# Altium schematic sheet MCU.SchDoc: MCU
size 431 x 279 mm; DocumentNumber: 10000020916; Revision: 000; SheetNumber: 4; SheetTotal: 10; DESCRIPTION REVISION 1 LOG: RELEASE FOR PROTOTYPE; ProjectTitle: Industrial IOT Sensor
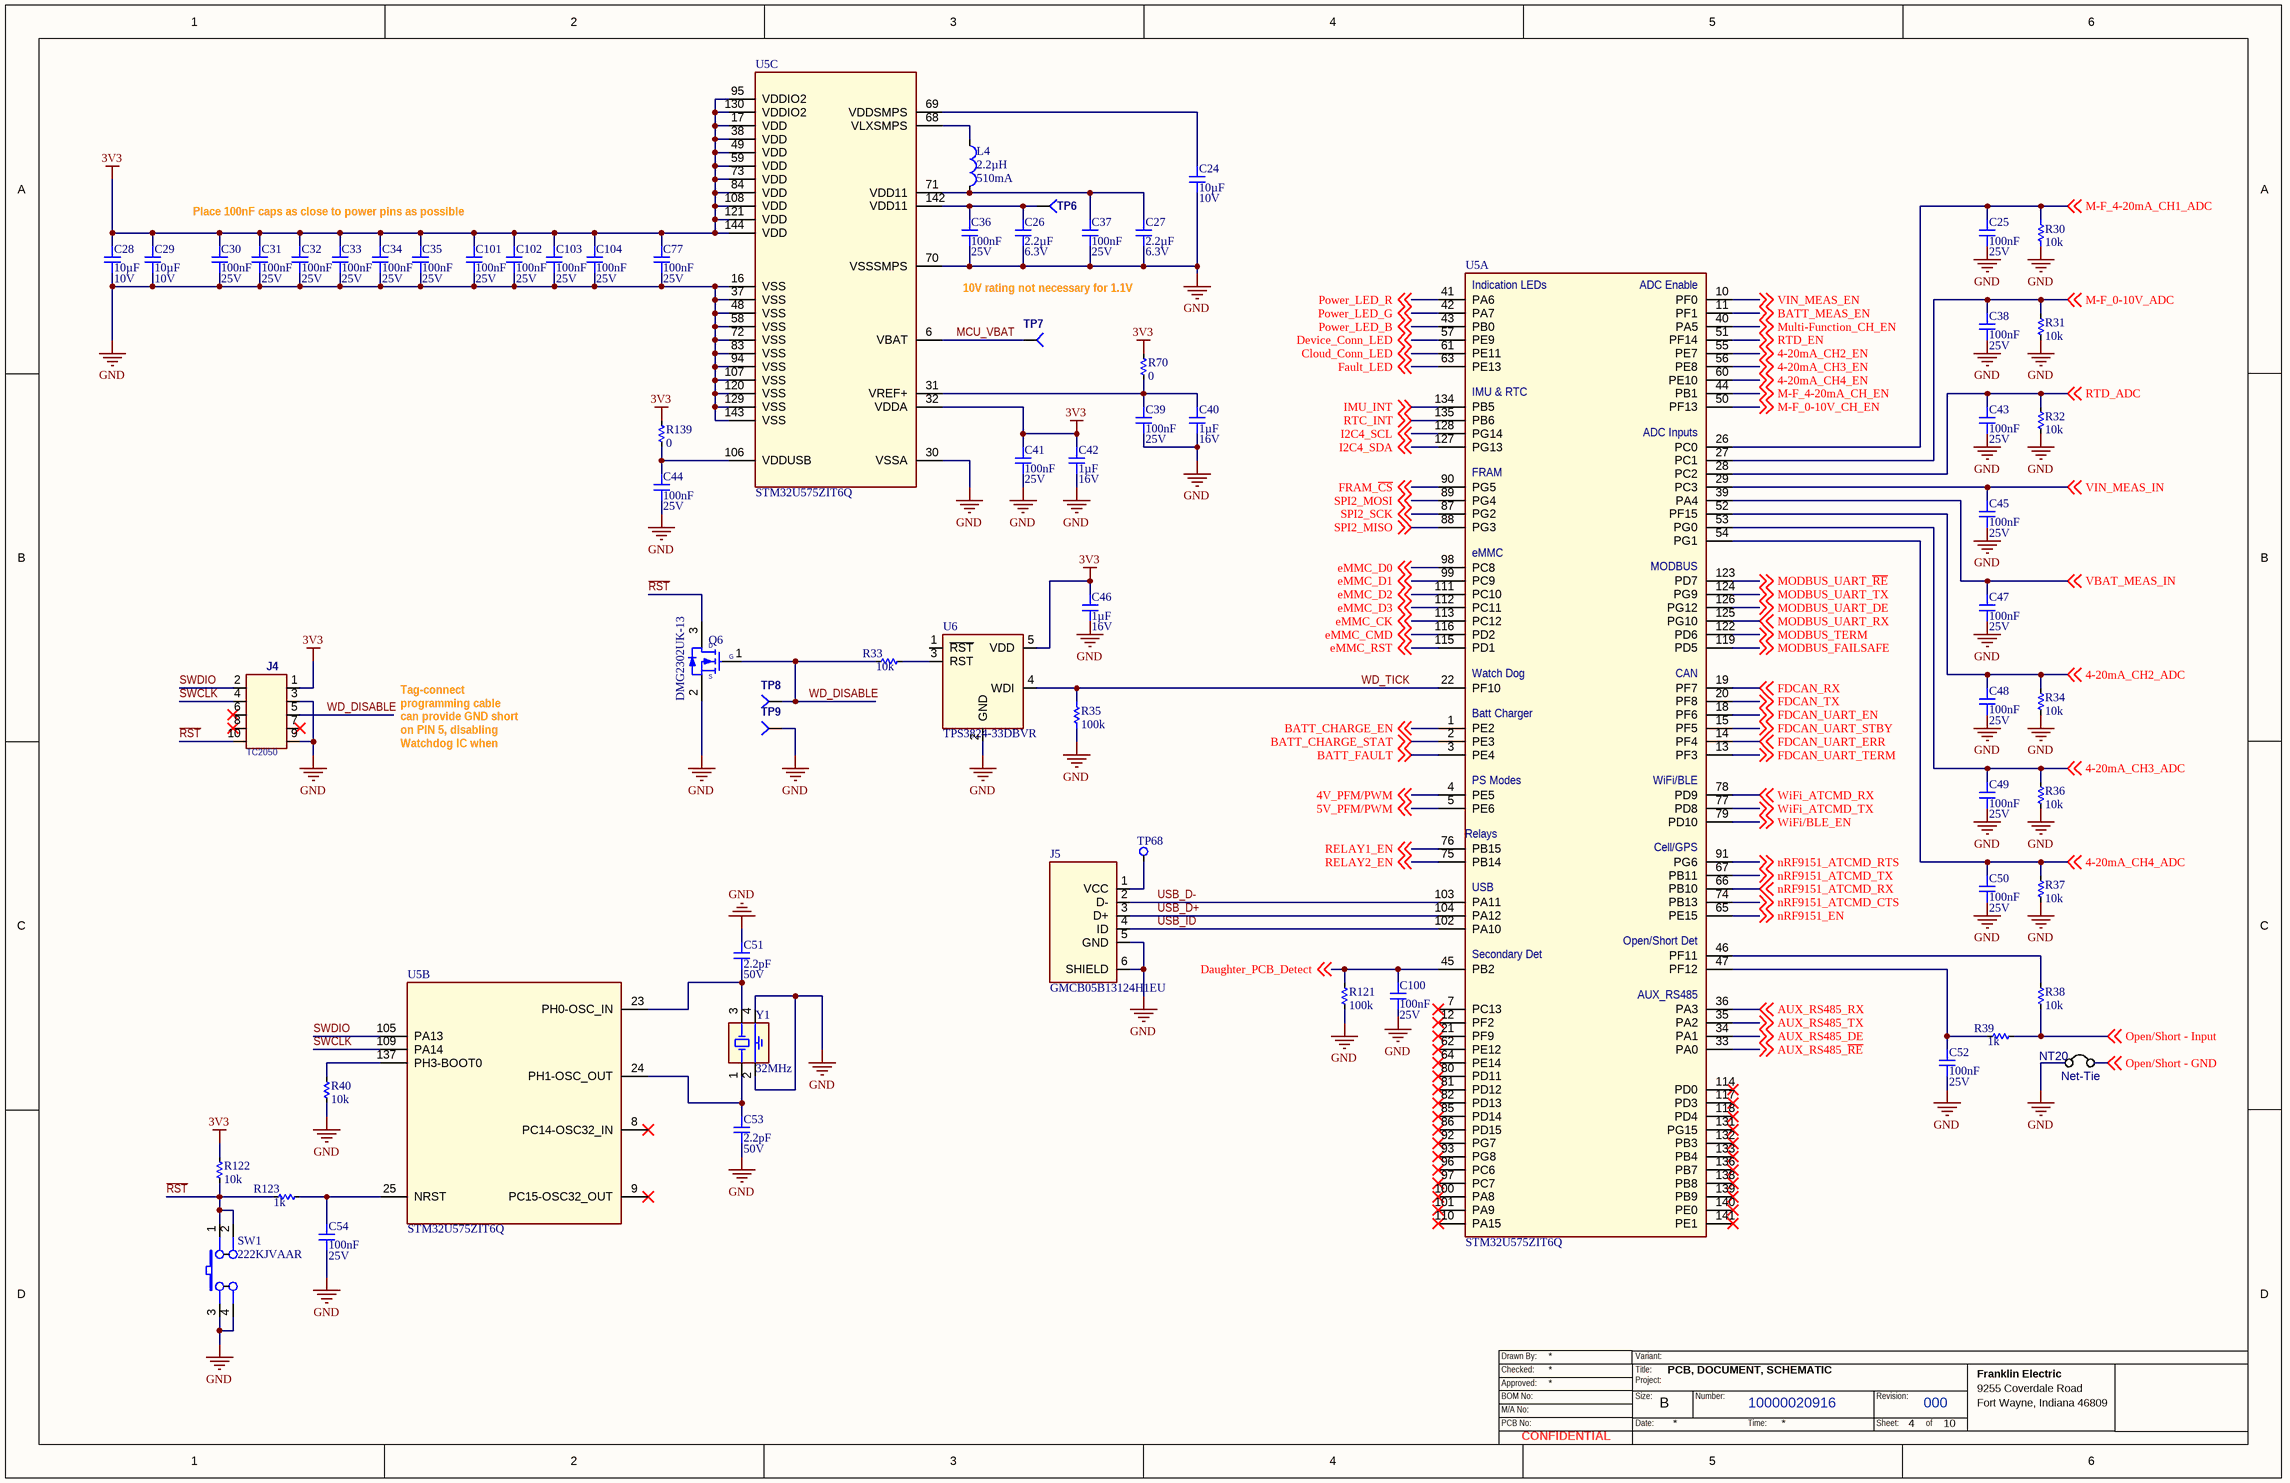
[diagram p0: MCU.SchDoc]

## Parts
C24  10µF  Voltage Rating DC: 10V  [CAPC1608X90N]
C25  100nF  Voltage Rating DC: 25V  [CAPC1005X60N]
C26  2.2µF  Voltage Rating DC: 6.3V  [CAPC1005X60N]
C27  2.2µF  Voltage Rating DC: 6.3V  [CAPC1005X60N]
C28  10µF  Voltage Rating DC: 10V  [CAPC1608X90N]
C29  10µF  Voltage Rating DC: 10V  [CAPC1608X90N]
C30  100nF  Voltage Rating DC: 25V  [CAPC1005X60N]
C31  100nF  Voltage Rating DC: 25V  [CAPC1005X60N]
C32  100nF  Voltage Rating DC: 25V  [CAPC1005X60N]
C33  100nF  Voltage Rating DC: 25V  [CAPC1005X60N]
C34  100nF  Voltage Rating DC: 25V  [CAPC1005X60N]
C35  100nF  Voltage Rating DC: 25V  [CAPC1005X60N]
C36  100nF  Voltage Rating DC: 25V  [CAPC1005X60N]
C37  100nF  Voltage Rating DC: 25V  [CAPC1005X60N]
C38  100nF  Voltage Rating DC: 25V  [CAPC1005X60N]
C39  100nF  Voltage Rating DC: 25V  [CAPC1005X60N]
C40  1µF  Voltage Rating DC: 16V  [CAPC1005X60N]
C41  100nF  Voltage Rating DC: 25V  [CAPC1005X60N]
C42  1µF  Voltage Rating DC: 16V  [CAPC1005X60N]
C43  100nF  Voltage Rating DC: 25V  [CAPC1005X60N]
C44  100nF  Voltage Rating DC: 25V  [CAPC1005X60N]
C45  100nF  Voltage Rating DC: 25V  [CAPC1005X60N]
C46  1µF  Voltage Rating DC: 16V  [CAPC1005X60N]
C47  100nF  Voltage Rating DC: 25V  [CAPC1005X60N]
C48  100nF  Voltage Rating DC: 25V  [CAPC1005X60N]
C49  100nF  Voltage Rating DC: 25V  [CAPC1005X60N]
C50  100nF  Voltage Rating DC: 25V  [CAPC1005X60N]
C51  2.2pF  Voltage Rating DC: 50V  [CAPC1005X60N]
C52  100nF  Voltage Rating DC: 25V  [CAPC1005X60N]
C53  2.2pF  Voltage Rating DC: 50V  [CAPC1005X60N]
C54  100nF  Voltage Rating DC: 25V  [CAPC1005X60N]
C77  100nF  Voltage Rating DC: 25V  [CAPC1005X60N]
C100  100nF  Voltage Rating DC: 25V  [CAPC1005X60N]
C101  100nF  Voltage Rating DC: 25V  [CAPC1005X60N]
C102  100nF  Voltage Rating DC: 25V  [CAPC1005X60N]
C103  100nF  Voltage Rating DC: 25V  [CAPC1005X60N]
C104  100nF  Voltage Rating DC: 25V  [CAPC1005X60N]
J4  value TC2050  [TC2050_NL]  (hidden comment: J_CONN TC2050)  (no BOM)
J5  GMCB05B13124H1EU  [USB 2.0 MICRO B]
L4  2.2µH  Rated Current: 510mA  [INDA251818-A]
NT20  Net-Tie  [NT-40mil-No Mask/No Silk]  (net tie, no BOM)
Q6  DMG2302UK-13  [SOT90P225X100-3N]
R30  10k  [RESC1005N]
R31  10k  [RESC1005N]
R32  10k  [RESC1005N]
R33  10k  [RESC1005N]
R34  10k  [RESC1005N]
R35  100k  [RESC1005N]
R36  10k  [RESC1005N]
R37  10k  [RESC1005N]
R38  10k  [RESC1005N]
R39  1k  [RESC1005N]
R40  10k  [RESC1005N]
R70  0  [RESC1005N]
R121  100k  [RESC1005N]
R122  10k  [RESC1005N]
R123  1k  [RESC1005N]
R139  0  [RESC1005N]
SW1  222KJVAAR  [6.2x6.2x5.2 Tactile SW J-Lead]
TP6  TEST POINT, SMD PAD, .050 DIA  [TESTPOINT_SMD_ROUND_50]  (value not drawn)
TP7  TEST POINT, SMD PAD, .050 DIA  [TESTPOINT_SMD_ROUND_50]  (value not drawn)
TP8  TEST POINT, SMD PAD, .050 DIA  [TESTPOINT_SMD_ROUND_50]  (value not drawn)
TP9  TEST POINT, SMD PAD, .050 DIA  [TESTPOINT_SMD_ROUND_50]  (value not drawn)
TP68  Test Points  [TP030SMD]  (value not drawn)  (no BOM)
U5  STM32U575ZIT6Q  [144-LQFP (20x20)]  (parts A,B,C of 3)
U6  TPS3824-33DBVR  [SOT23-5]
Y1  32MHz  [OSC4P200X160X59_ABM1132M-A]

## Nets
3V3: C28.1 C29.1 C30.1 C31.1 C32.1 C33.1 C34.1 C35.1 C41.1 C42.1 C46.1 C77.1 C101.1 C102.1 C103.1 C104.1 J4.1 R70.1 R122.1 R139.1 U5.17(VDD) U5.32(VDDA) U5.38(VDD) U5.49(VDD) U5.59(VDD) U5.73(VDD) U5.84(VDD) U5.95(VDDIO2) U5.108(VDD) U5.121(VDD) U5.130(VDDIO2) U5.144(VDD) U6.5(VDD)
GND: C24.2 C25.2 C26.2 C27.2 C28.2 C29.2 C30.2 C31.2 C32.2 C33.2 C34.2 C35.2 C36.2 C37.2 C38.2 C39.2 C40.2 C41.2 C42.2 C43.2 C44.2 C45.2 C46.2 C47.2 C48.2 C49.2 C50.2 C51.1 C52.2 C53.2 C54.2 C77.2 C100.2 C101.2 C102.2 C103.2 C104.2 J4.3 J4.9 J5.5(GND) J5.6(SHIELD) NT20.1 Q6.2(Source) R30.2 R31.2 R32.2 R34.2 R35.2 R36.2 R37.2 R40.2 R121.2 SW1.3 SW1.4 TP9.1(TP) U5.16(VSS) U5.30(VSSA) U5.37(VSS) U5.48(VSS) U5.58(VSS) U5.70(VSSSMPS) U5.72(VSS) U5.83(VSS) U5.94(VSS) U5.107(VSS) U5.120(VSS) U5.129(VSS) U5.143(VSS) U6.2(GND) Y1.2(GND) Y1.4(GND)
4-20mA_CH2_ADC: C48.1 R34.1 U5.52(PF15) ; off-sheet 4-20mA_CH2_ADC
4-20mA_CH2_EN: U5.55(PE7) ; off-sheet 4-20mA_CH2_EN
4-20mA_CH3_ADC: C49.1 R36.1 U5.53(PG0) ; off-sheet 4-20mA_CH3_ADC
4-20mA_CH3_EN: U5.56(PE8) ; off-sheet 4-20mA_CH3_EN
4-20mA_CH4_ADC: C50.1 R37.1 U5.54(PG1) ; off-sheet 4-20mA_CH4_ADC
4-20mA_CH4_EN: U5.60(PE10) ; off-sheet 4-20mA_CH4_EN
4V_PFM/PWM: U5.4(PE5) ; off-sheet 4V_PFM/PWM
5V_PFM/PWM: U5.5(PE6) ; off-sheet 5V_PFM/PWM
AUX_RS485_DE: U5.34(PA1) ; off-sheet AUX_RS485_DE
AUX_RS485_~{RE}: U5.33(PA0) ; off-sheet AUX_RS485_~{RE}
AUX_RS485_RX: U5.36(PA3) ; off-sheet AUX_RS485_RX
AUX_RS485_TX: U5.35(PA2) ; off-sheet AUX_RS485_TX
BATT_CHARGE_EN: U5.1(PE2) ; off-sheet BATT_CHARGE_EN
BATT_CHARGE_STAT: U5.2(PE3) ; off-sheet BATT_CHARGE_STAT
BATT_FAULT: U5.3(PE4) ; off-sheet BATT_FAULT
BATT_MEAS_EN: U5.11(PF1) ; off-sheet BATT_MEAS_EN
Cloud_Conn_LED: U5.61(PE11) ; off-sheet Cloud_Conn_LED
Daughter_PCB_Detect: C100.1 R121.1 U5.45(PB2) ; off-sheet Daughter_PCB_Detect
Device_Conn_LED: U5.57(PE9) ; off-sheet Device_Conn_LED
eMMC_CK: U5.113(PC12) ; off-sheet eMMC_CK
eMMC_CMD: U5.116(PD2) ; off-sheet eMMC_CMD
eMMC_D0: U5.98(PC8) ; off-sheet eMMC_D0
eMMC_D1: U5.99(PC9) ; off-sheet eMMC_D1
eMMC_D2: U5.111(PC10) ; off-sheet eMMC_D2
eMMC_D3: U5.112(PC11) ; off-sheet eMMC_D3
eMMC_RST: U5.115(PD1) ; off-sheet eMMC_RST
Fault_LED: U5.63(PE13) ; off-sheet Fault_LED
FDCAN_RX: U5.19(PF7) ; off-sheet FDCAN_RX
FDCAN_TX: U5.20(PF8) ; off-sheet FDCAN_TX
FDCAN_UART_EN: U5.18(PF6) ; off-sheet FDCAN_UART_EN
FDCAN_UART_ERR: U5.14(PF4) ; off-sheet FDCAN_UART_ERR
FDCAN_UART_STBY: U5.15(PF5) ; off-sheet FDCAN_UART_STBY
FDCAN_UART_TERM: U5.13(PF3) ; off-sheet FDCAN_UART_TERM
FRAM_~{CS}: U5.90(PG5) ; off-sheet FRAM_~{CS}
I2C4_SCL: U5.128(PG14) ; off-sheet I2C4_SCL
I2C4_SDA: U5.127(PG13) ; off-sheet I2C4_SDA
IMU_INT: U5.134(PB5) ; off-sheet IMU_INT
M-F_0-10V_ADC: C38.1 R31.1 U5.27(PC1) ; off-sheet M-F_0-10V_ADC
M-F_0-10V_CH_EN: U5.50(PF13) ; off-sheet M-F_0-10V_CH_EN
M-F_4-20mA_CH1_ADC: C25.1 R30.1 U5.26(PC0) ; off-sheet M-F_4-20mA_CH1_ADC
M-F_4-20mA_CH_EN: U5.44(PB1) ; off-sheet M-F_4-20mA_CH_EN
MCU_VBAT: TP7.1(TP) U5.6(VBAT)
MODBUS_FAILSAFE: U5.119(PD5) ; off-sheet MODBUS_FAILSAFE
MODBUS_TERM: U5.122(PD6) ; off-sheet MODBUS_TERM
MODBUS_UART_DE: U5.126(PG12) ; off-sheet MODBUS_UART_DE
MODBUS_UART_~{RE}: U5.123(PD7) ; off-sheet MODBUS_UART_~{RE}
MODBUS_UART_RX: U5.125(PG10) ; off-sheet MODBUS_UART_RX
MODBUS_UART_TX: U5.124(PG9) ; off-sheet MODBUS_UART_TX
Multi-Function_CH_EN: U5.40(PA5) ; off-sheet Multi-Function_CH_EN
nRF9151_ATCMD_CTS: U5.74(PB13) ; off-sheet nRF9151_ATCMD_CTS
nRF9151_ATCMD_RTS: U5.91(PG6) ; off-sheet nRF9151_ATCMD_RTS
nRF9151_ATCMD_RX: U5.66(PB10) ; off-sheet nRF9151_ATCMD_RX
nRF9151_ATCMD_TX: U5.67(PB11) ; off-sheet nRF9151_ATCMD_TX
nRF9151_EN: U5.65(PE15) ; off-sheet nRF9151_EN
Open/Short - GND: NT20.2 ; off-sheet Open/Short - GND
Open/Short - Input: R38.2 R39.2 ; off-sheet Open/Short - Input
Power_LED_B: U5.43(PB0) ; off-sheet Power_LED_B
Power_LED_G: U5.42(PA7) ; off-sheet Power_LED_G
Power_LED_R: U5.41(PA6) ; off-sheet Power_LED_R
~{RST}: J4.10 Q6.3(Drain) R122.2 R123.1 SW1.1 SW1.2
RELAY1_EN: U5.76(PB15) ; off-sheet RELAY1_EN
RELAY2_EN: U5.75(PB14) ; off-sheet RELAY2_EN
RTC_INT: U5.135(PB6) ; off-sheet RTC_INT
RTD_ADC: C43.1 R32.1 U5.28(PC2) ; off-sheet RTD_ADC
RTD_EN: U5.51(PF14) ; off-sheet RTD_EN
SPI2_MISO: U5.88(PG3) ; off-sheet SPI2_MISO
SPI2_MOSI: U5.89(PG4) ; off-sheet SPI2_MOSI
SPI2_SCK: U5.87(PG2) ; off-sheet SPI2_SCK
SWCLK: J4.4 U5.109(PA14)
SWDIO: J4.2 U5.105(PA13)
USB_D+: J5.3(D+) U5.104(PA12)
USB_D-: J5.2(D-) U5.103(PA11)
USB_ID: J5.4(ID) U5.102(PA10)
VBAT_MEAS_IN: C47.1 U5.39(PA4) ; off-sheet VBAT_MEAS_IN
VIN_MEAS_EN: U5.10(PF0) ; off-sheet VIN_MEAS_EN
VIN_MEAS_IN: C45.1 U5.29(PC3) ; off-sheet VIN_MEAS_IN
WD_DISABLE: J4.5 Q6.1(Gate) R33.1 TP8.1(TP)
WD_TICK: R35.1 U5.22(PF10) U6.4(WDI)
WiFi/BLE_EN: U5.79(PD10) ; off-sheet WiFi/BLE_EN
WiFi_ATCMD_RX: U5.78(PD9) ; off-sheet WiFi_ATCMD_RX
WiFi_ATCMD_TX: U5.77(PD8) ; off-sheet WiFi_ATCMD_TX
NetC24_1: C24.1 U5.69(VDDSMPS)
NetC26_1: C26.1 C36.1 TP6.1(TP) U5.142(VDD11)
NetC27_1: C27.1 C37.1 L4.2 U5.71(VDD11)
NetC39_1: C39.1 C40.1 R70.2 U5.31(VREF+)
NetC44_1: C44.1 R139.2 U5.106(VDDUSB)
NetC51_2: C51.2 U5.23(PH0-OSC_IN) Y1.3(X)
NetC52_1: C52.1 R39.1 U5.47(PF12)
NetC53_1: C53.1 U5.24(PH1-OSC_OUT) Y1.1(X)
NetC54_1: C54.1 R123.2 U5.25(NRST)
NetJ5_1: J5.1(VCC) TP68.1
NetL4_1: L4.1 U5.68(VLXSMPS)
NetR33_2: R33.2 U6.3(RST)
NetR38_1: R38.1 U5.46(PF11)
NetR40_1: R40.1 U5.137(PH3-BOOT0)

Not connected (* = marked no-connect by the designer): J4 6* 7* 8*; U5 7(PC13)* 8(PC14-OSC32_IN)* 9(PC15-OSC32_OUT)* 12(PF2)* 21(PF9)* 62(PE12)* 64(PE14)* 80(PD11)* 81(PD12)* 82(PD13)* 85(PD14)* 86(PD15)* 92(PG7)* 93(PG8)* 96(PC6)* 97(PC7)* 100(PA8)* 101(PA9)* 110(PA15)* 114(PD0)* 117(PD3)* 118(PD4)* 131(PG15)* 132(PB3)* 133(PB4)* 136(PB7)* 138(PB8)* 139(PB9)* 140(PE0)* 141(PE1)*; U6 1(~{RST})

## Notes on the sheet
- Place 100nF caps as close to power pins as possible
- 10V rating not necessary for 1.1V rail
- Tag-connect programming cable can provide GND short on PIN 5, disabling Watchdog IC when connected

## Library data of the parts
C24 C28 C29 = CMP-003-0109-42: CAP CER SMD 0603 10V 10% 10uF X5R; MFR1: Murata; MFR2PN: CL10A106KP8NNND; MFR3PN: 0603X106K100CT; MFR1PN: GRM188R61A106KE69D; FEPN: 227000148; Op Temp Max: 85°C; Agency Restriction: No; Op Temp Min: -55°C
C25 C30-C39 C41 C43-C45 C47-C50 C52 C54 C77 C100-C104 = CMP-00599-2: CAP CER SMD 0402 (1005) 25V 10% 0.1UF X7R; MFR2PN: 04023C104KAT2A; MFR1PN: CGA2B3X7R1E104K; MFR3PN: CL05B104KA5NNNC; MFR1: TDK; MFR4PN: TMK105B7104KVHF; FEPN: 228685108; Agency Restriction: N; Op Temp Min: -55°C; Op Temp Max: 125°C; Voltage Rating AC: 0V
C26 C27 = CMP-01677-1: CAP CER SMD 0402 6.3V 10% 2.2uF X5R; MFR1PN: CC0402KRX5R6BB225; MFR1: YAGEO; Agency Restriction: None; Op Temp Min: -55°C; Op Temp Max: 85°C; Voltage Rating AC: 0V; FEPN: 10000022637
C40 C42 C46 = CMP-019-0104-35: CAP CER SMD 0402 16V 10% 1UF X7R; MFR3PN: EMK105BJ105KV-F; MFR1PN: CL05A105KL5NRNC; MFR4PN: C1005X5R1C105K050BC; MFR2PN: EMK105BJ105KVHF; MFR1: Samsung; FEPN: 228685109; Agency Restriction: No; Op Temp Min: -55°C; Op Temp Max: 85°C
C51 C53 = CMP-01678-1: CAP CER SMD  0402 50V +/-.25pF 2.2pF C0G; MFR1PN: GJM1555C1H2R2CB01D; MFR1: MURATA; Agency Restriction: None; Op Temp Max: 125°C; FEPN: 10000022638; Op Temp Min: -55°C; Tolerance: 0%
J4 = J_CONN TC2050: DNA - TC2030-MCP Plug-of-Nails Programming Terminals (PCB Feature)(Do Not Assemble); Part_Type: Miscellaneous; FPLIST: TC2030,TC2030_SP
J5 = CMP-01736-2: CONNECTOR, INTERFACE, USBUB USB2.0 POST VERTICAL; MFR1: AMPHENOL; Current Rating: 1.8A; Agency Restriction: None; Op Temp Max: 85°C; FEPN: 10000023422; Op Temp Min: -40°C; Number Of Positions: 5; Voltage Rating: 30V
L4 = CMP-01703-2: INDUCTOR, FIXED, SURFACE MOUNT 2.2uH 510mA 117mOHM; MFR1: TAIYO YUDEN; MFR1PN: LSQNA251818T2R2M; FEPN: 10000023000; Saturation Current: 950mA; Tolerance: 20%; Type: Unshielded Wirewound; Op Temp Max: 105°C; Agency Restriction: N; Op Temp Min: -40°C
NT20 = CMP-058-0000-6
Q6 = CMP-01724-2: TRANSISTOR, FET, N 20V 2.8A SOT23 SMD; MFR1: DIODES INC; Op Temp Max: 150°C; FEPN: 10000023201; Op Temp Min: -55°C; Type: MOSFET
R30 = CMP-01594-1: RESISTOR, SMD, THCK FLM ASR 0402 100mW 1% 10K OHM; MFR1PN: RNCP0402FTD10K0; MFR1: STACKPOLE; Agency Restriction: None; Op Temp Min: -55°C; FEPN: 10000021217; Temperature Coefficient: ±200ppm/°C; Op Temp Max: 155°C
R31-R34 R36-R38 R40 R122 = CMP-01594-4: RESISTOR, SMD, THCK FLM ASR 0402 100mW 1% 10K OHM; MFR1PN: RNCP0402FTD10K0; MFR1: STACKPOLE; Agency Restriction: None; Op Temp Min: -55°C; FEPN: 10000021217; Temperature Coefficient: ±200ppm/°C; Op Temp Max: 155°C
R35 = CMP-01591-1: RESISTOR, SMD, THCK FLM ASR 0402 100mW 1% 100K OHM; MFR1: PANASONIC; MFR1PN: ERJ-U02F1003X; FEPN: 10000021214; Agency Restriction: None; Op Temp Max: 155°C; Op Temp Min: -55°C; Temperature Coefficient: ±200ppm/°C
R39 R123 = CMP-01603-4: RESISTOR, SMD, THN FLM ASR 0402 100mW 1% 1K OHM; MFR1: STACKPOLE; MFR1PN: RNCP0402FTD1K00; Op Temp Max: 155°C; FEPN: 10000021229; Temperature Coefficient: ±200ppm/°C; Agency Restriction: None; Op Temp Min: -55°C
R70 R139 = CMP-01604-3: RESISTOR, SMD, THCK FLM ASR 0402 100mW 1% 0 OHM; MFR1PN: ERJ-U020R00X; MFR1: PANASONIC; Op Temp Max: 155°C; FEPN: 10000021231; Agency Restriction: None; Temperature Coefficient: ±200ppm/°C; Op Temp Min: -55°C
R121 = CMP-01591-4: RESISTOR, SMD, THCK FLM ASR 0402 100mW 1% 100K OHM; MFR1: PANASONIC; MFR1PN: ERJ-U02F1003X; FEPN: 10000021214; Agency Restriction: None; Op Temp Max: 155°C; Op Temp Min: -55°C; Temperature Coefficient: ±200ppm/°C
SW1 = CMP-01730-1: SWITCH, TACTILE, SURFACE MOUNT SPST-NO 0.05A 32V J-LEAD; MFR1: CTS; Agency Restriction: N; Positions: 1; Lifecyle Status: Active; FEPN: 10000023217; Current Rating: 50mA; Op Temp Min: -40°C; Op Temp Max: 85°C
TP6-TP9 = TEST POINT, SMD PAD, .050 DIA: TESTPOINT, SMD PAD, .050 DIA; Placement: NP
TP68 = CMP-ROOT-0001-.61
U5 = CMP-01742-2: INTEGRATED CIRCUIT, MCU 32BIT 2MB FLASH 144LQFP SMD; MFR1: ST MICRO; Op Temp Min: -40; Op Temp Max: 85; FEPN: 10000023432; Agency Restriction: N
U6 = CMP-01743-1: INTEGRATED CIRCUIT, PMIC, SPRV 1 CHANNEL SOT23-5 SMD; MFR1: TI; Nominal Voltage: 2.93V; Op Temp Min: -40°C; SubType: Push-Pull, Totem Pole; Agency Restriction: N; FEPN: 10000023433; Op Temp Max: 85°C
Y1 = CMP-01707-3: OSCILLATOR, CRYSTAL, SMD 32MHz 10pF 4-PIN NO LEAD; MFR1: ABRACOM; MFR1PN: ABM11-32.000MHZ-B7G-T; FEPN: 10000023116; Op Temp Max: 70°C; Op Temp Min: -20°C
